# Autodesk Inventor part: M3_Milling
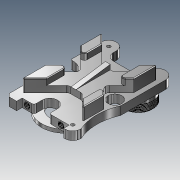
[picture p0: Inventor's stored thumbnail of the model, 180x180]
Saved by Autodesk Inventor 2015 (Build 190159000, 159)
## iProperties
Created: 2015-04
Part Number: M3_Milling
Material: Aço
Document SubType Name: Modeling
Designer: Andrew Almeida
Density: 7.85 g/cm^3
Appearance: Placa
Title: C:/Users/Andrew Almeida/Documents/Projeto WS2015/WS2015 CAD Data ANLAS/07/#07 - CNC Milling/01 - 3D Models/M3_Milling.stp
Creation Date: 2015-04-23
Sending System: Autodesk Translation Framework v4.0.0.5211
Preprocessor: ST-DEVELOPER v16.1
Author: Andrew Almeida
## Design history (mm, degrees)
node "M3_Milling1"
feature "Rosca1" dims "d0" = 10, "d1" = 0
feature "Rosca2" dims "d2" = 16, "d3" = 0
feature "Rosca3" dims "d4" = 16, "d5" = 0
sketch "Esboço2"
  geometry: L1 (21, 0)-(21, 10); L2 (21, 10)-(20.259, 10); L3 (20.259, 10)-(20.259, 0); L4 (20.259, 0)-(21, 0); L5 (0, -11.6)-(0, 55.6) reference
  constraints: 8 end point
revolve "Revolução1" sketch "Esboço2" stored, may be unused: angle "d15" = 0 deg
sketch "Esboço3"
  geometry: L1 (21, 0)-(21, 10); L2 (21, 10)-(20.259, 10); L3 (20.259, 10)-(20.259, 0); L4 (20.259, 0)-(21, 0); L5 (0, -11.6)-(0, 55.6) reference
  constraints: 8 end point
revolve "Revolução2" sketch "Esboço3" stored, may be unused: angle "d16" = 0 deg
sketch "Esboço1"
  geometry: L1 (-0.583, -20.309)-(-0.5, -20.309); L2 (0.083, -20.95)-(0, -21.11); L3 (-1, -21.11)-(-1.083, -20.95); L4 (-0.417, -20.309)-(-0.5, -20.149); L5 (-0.5, -20.149)-(-0.583, -20.309); L6 (-1, -21.11)-(-0.917, -20.95); L7 (-0.417, -20.309)-(-0.083, -20.95); L8 (-1.083, -20.95)-(-0.917, -20.95); L9 (0.083, -20.95)-(-0.083, -20.95); L10 (-1, -21.11)-(-1, -20.95); L11 (0, -21.11)-(0, -20.95); L12 (-0.5, -20.149)-(-0.5, -20.259); L13 (-1, -21)-(0, -21); L14 (-0.083, -20.95)-(0, -21.11); L15 (-0.917, -20.95)-(-0.583, -20.309); L16 (0, 0)-(0, 0.018); L17 (0, 0.018)-(0, 0); L18 (0, 0)-(0.033, 0); L19 (-0.5, -20.259)-(-0.5, -20.309); L20 (-0.5, -20.309)-(-0.417, -20.309); A1 r 0.094 centre (-1, -20.906) between (-1.083, -20.95) and (-1, -21); A2 r 0.094 centre (-1, -20.906) between (-1, -21) and (-0.917, -20.95); A3 r 0.094 centre (0, -20.906) between (-0.083, -20.95) and (0, -21); A4 r 0.094 centre (0, -20.906) between (0, -21) and (0.083, -20.95); A5 r 0.094 centre (-0.5, -20.353) between (-0.5, -20.259) and (-0.583, -20.309); A6 r 0.094 centre (-0.5, -20.353) between (-0.417, -20.309) and (-0.5, -20.259)
  constraints: 40 end point, 12 point on circle, 10 parallel, 8 tangent, 6 centre point, 6 collinear, 2 midpoint, 2 point on line, 1 horizontal, 1 perpendicular, 3 other
  dimensions: "d6" = 55 deg angle of L7 L15 (= d13); "d7" = 0.16008 distance of L4.end L1.end (= 0.160083 x Esboço1_Pitch); "d8" = 0.16008 distance of L2.end L11.end (= 0.160083 x Esboço1_Pitch); "Esboço1_ThreadOffset" = 0 distance between parallel lines of L16 L11; "Esboço1_MajorRadius" = 21 distance from line of L13 L16.start; "d11" = 1 distance from line of L2.end L10 (= Esboço1_Pitch); "Esboço1_MinorRadius" = 20.25854 distance edge to line of A6 L18 (derived)
feature "Espiral1" sketch "Esboço1" pitch "d17" = 1.5015; turns "d19" = 1; dims "d18" = 13, "d20" = 0, angle "d21" = 0 deg, angle "d22" = 0 deg, "d23" = 0, "d24" = 0
sketch "Esboço5"
  geometry: L1 (4.188, 0)-(4.188, 16); L2 (4.188, 16)-(3.447, 16); L3 (3.447, 16)-(3.447, 0); L4 (3.447, 0)-(4.188, 0); L5 (0, -37.2)-(0, 167.2) reference
  constraints: 8 end point
revolve "Revolução3" sketch "Esboço5" stored, may be unused: angle "d34" = 0 deg
sketch "Esboço4"
  geometry: L1 (-0.583, -0.051)-(-0.5, -0.051); L2 (0.083, -0.691)-(0, -0.851); L3 (-1, -0.851)-(-1.083, -0.691); L4 (-0.417, -0.051)-(-0.5, 0.109); L5 (-0.5, 0.109)-(-0.583, -0.051); L6 (-1, -0.851)-(-0.917, -0.691); L7 (-0.417, -0.051)-(-0.083, -0.691); L8 (-1.083, -0.691)-(-0.917, -0.691); L9 (0.083, -0.691)-(-0.083, -0.691); L10 (-1, -0.851)-(-1, -0.691); L11 (0, -0.851)-(0, -0.691); L12 (-0.5, 0.109)-(-0.5, 0); L13 (-1, -0.742)-(0, -0.742); L14 (-0.083, -0.691)-(0, -0.851); L15 (-0.917, -0.691)-(-0.583, -0.051); L16 (0, 0)-(0, 0.018); L17 (0, 0.018)-(0, 0); L18 (0, 0)-(0.033, 0); L19 (-0.5, 0)-(-0.5, -0.051); L20 (-0.5, -0.051)-(-0.417, -0.051); A1 r 0.094 centre (-1, -0.648) between (-1.083, -0.691) and (-1, -0.742); A2 r 0.094 centre (-1, -0.648) between (-1, -0.742) and (-0.917, -0.691); A3 r 0.094 centre (0, -0.648) between (-0.083, -0.691) and (0, -0.742); A4 r 0.094 centre (0, -0.648) between (0, -0.742) and (0.083, -0.691); A5 r 0.094 centre (-0.5, -0.094) between (-0.5, 0) and (-0.583, -0.051); A6 r 0.094 centre (-0.5, -0.094) between (-0.417, -0.051) and (-0.5, 0)
  constraints: 40 end point, 12 point on circle, 10 parallel, 8 tangent, 6 centre point, 6 collinear, 2 midpoint, 2 point on line, 1 horizontal, 1 perpendicular, 3 other
  dimensions: "d25" = 55 deg angle of L7 L15 (= d32); "d26" = 0.16008 distance of L4.end L1.end (= 0.160083 x Esboço4_Pitch); "d27" = 0.16008 distance of L2.end L11.end (= 0.160083 x Esboço4_Pitch); "Esboço4_ThreadOffset" = 0 distance between parallel lines of L16 L11; "Esboço4_MajorRadius" = 0.74146 distance from line of L13 L16.start; "d30" = 1 distance from line of L2.end L10 (= Esboço4_Pitch); "Esboço4_MinorRadius" = 0 distance edge to line of A6 L18 (derived)
feature "Espiral2" sketch "Esboço4" pitch "d35" = 1.5015; turns "d37" = 1; dims "d36" = 19, "d38" = 0, angle "d39" = 0 deg, angle "d40" = 0 deg, "d41" = 0, "d42" = 0
sketch "Esboço7"
  geometry: L1 (4.188, 0)-(4.188, 16); L2 (4.188, 16)-(3.447, 16); L3 (3.447, 16)-(3.447, 0); L4 (3.447, 0)-(4.188, 0); L5 (0, -37.2)-(0, 167.2) reference
  constraints: 8 end point
revolve "Revolução4" sketch "Esboço7" stored, may be unused: angle "d52" = 0 deg
sketch "Esboço6"
  geometry: L1 (-0.583, -0.051)-(-0.5, -0.051); L2 (0.083, -0.691)-(0, -0.851); L3 (-1, -0.851)-(-1.083, -0.691); L4 (-0.417, -0.051)-(-0.5, 0.109); L5 (-0.5, 0.109)-(-0.583, -0.051); L6 (-1, -0.851)-(-0.917, -0.691); L7 (-0.417, -0.051)-(-0.083, -0.691); L8 (-1.083, -0.691)-(-0.917, -0.691); L9 (0.083, -0.691)-(-0.083, -0.691); L10 (-1, -0.851)-(-1, -0.691); L11 (0, -0.851)-(0, -0.691); L12 (-0.5, 0.109)-(-0.5, 0); L13 (-1, -0.742)-(0, -0.742); L14 (-0.083, -0.691)-(0, -0.851); L15 (-0.917, -0.691)-(-0.583, -0.051); L16 (0, 0)-(0, 0.018); L17 (0, 0.018)-(0, 0); L18 (0, 0)-(0.033, 0); L19 (-0.5, 0)-(-0.5, -0.051); L20 (-0.5, -0.051)-(-0.417, -0.051); A1 r 0.094 centre (-1, -0.648) between (-1.083, -0.691) and (-1, -0.742); A2 r 0.094 centre (-1, -0.648) between (-1, -0.742) and (-0.917, -0.691); A3 r 0.094 centre (0, -0.648) between (-0.083, -0.691) and (0, -0.742); A4 r 0.094 centre (0, -0.648) between (0, -0.742) and (0.083, -0.691); A5 r 0.094 centre (-0.5, -0.094) between (-0.5, 0) and (-0.583, -0.051); A6 r 0.094 centre (-0.5, -0.094) between (-0.417, -0.051) and (-0.5, 0)
  constraints: 40 end point, 12 point on circle, 10 parallel, 8 tangent, 6 centre point, 6 collinear, 2 midpoint, 2 point on line, 1 horizontal, 1 perpendicular, 3 other
  dimensions: "d43" = 55 deg angle of L7 L15 (= d50); "d44" = 0.16008 distance of L4.end L1.end (= 0.160083 x Esboço6_Pitch); "d45" = 0.16008 distance of L2.end L11.end (= 0.160083 x Esboço6_Pitch); "Esboço6_ThreadOffset" = 0 distance between parallel lines of L16 L11; "Esboço6_MajorRadius" = 0.74146 distance from line of L13 L16.start; "d48" = 1 distance from line of L2.end L10 (= Esboço6_Pitch); "Esboço6_MinorRadius" = 0 distance edge to line of A6 L18 (derived)
feature "Espiral3" sketch "Esboço6" pitch "d53" = 1.5015; turns "d55" = 1; dims "d54" = 19, "d56" = 0, angle "d57" = 0 deg, angle "d58" = 0 deg, "d59" = 0, "d60" = 0
node "Body1"
node "Base1"
node "Sólido2"
node "Sólido3"
node "Sólido4"
other parameters: "d13" = 55 deg [user parameter; used in 1 equation term], "Esboço1_Pitch" = 1 [user parameter; used in 3 equation terms], "d32" = 55 deg [user parameter; used in 1 equation term], "Esboço4_Pitch" = 1 [user parameter; used in 3 equation terms], "d50" = 55 deg [user parameter; used in 1 equation term], "Esboço6_Pitch" = 1 [user parameter; used in 3 equation terms]
